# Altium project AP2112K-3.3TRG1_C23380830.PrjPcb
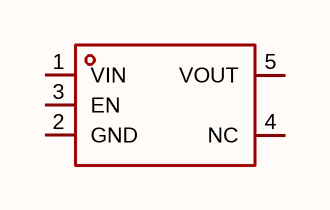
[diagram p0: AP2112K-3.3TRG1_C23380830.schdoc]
1 sheet, 1 parts. Net scope: global (net labels, ports and power ports of the same name join across sheets).

## Sheet AP2112K-3.3TRG1_C23380830.schdoc
size 127 x 101 mm

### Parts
U?  ap2112k-3.3trg1_c23380830  [SOT-23-5_L2.9-W1.6-P0.95-LS2.8-BR]  (value not drawn)

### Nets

Not connected (* = marked no-connect by the designer): U? 1(VIN) 2(GND) 3(EN) 4(NC) 5(VOUT)

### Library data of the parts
U? = ap2112k-3.3trg1_c23380830: 输出极性:正极;工作电压:5.5V;输出电压:3.3V;输出电流:600mA;电源纹波抑制比(PSRR):75dB@(1kHz);输出类型:固定;; Manufacturer: TECH PUBLIC(台舟); AddInBom: yes; ModelId: 7ba65df16e7b4570af156e925f9c37fe; ModelTransform: 114.173,114.173,0,90,0,0,0,0,0; Output Configuration: 正极; Voltage - Supply: 5.5V; Output Voltage: 3.3V; Output Current: 600mA; Voltage Dropout: 320mV@(600mA); standby current: 10uA; Output Type: 固定; Number of Outputs: 1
